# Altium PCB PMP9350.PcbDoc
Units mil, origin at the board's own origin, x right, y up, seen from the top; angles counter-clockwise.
Board outline 1440 x 2000 mil, 4 copper layers (Top Layer, MidLayer1, MidLayer2, Bottom Layer), stack 90 mil thick; 31 components, 13 nets, 63 pads, 44 vias.
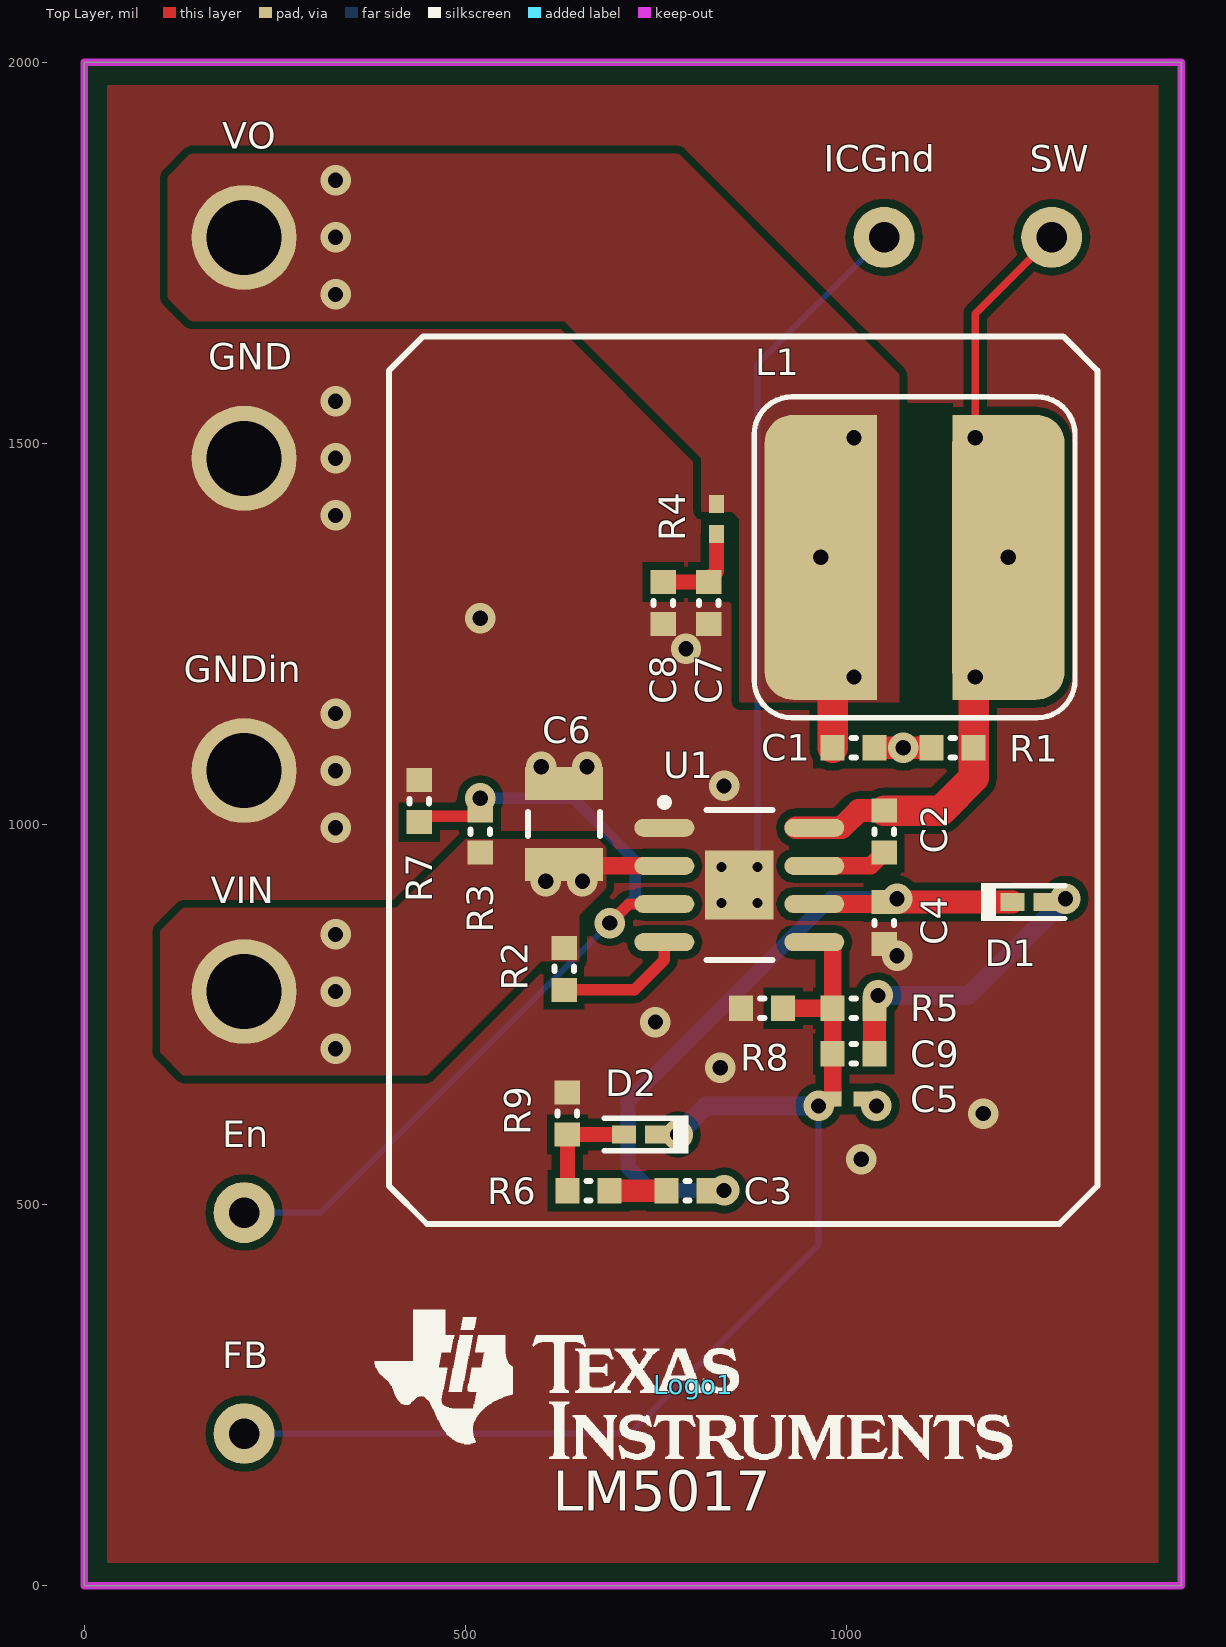
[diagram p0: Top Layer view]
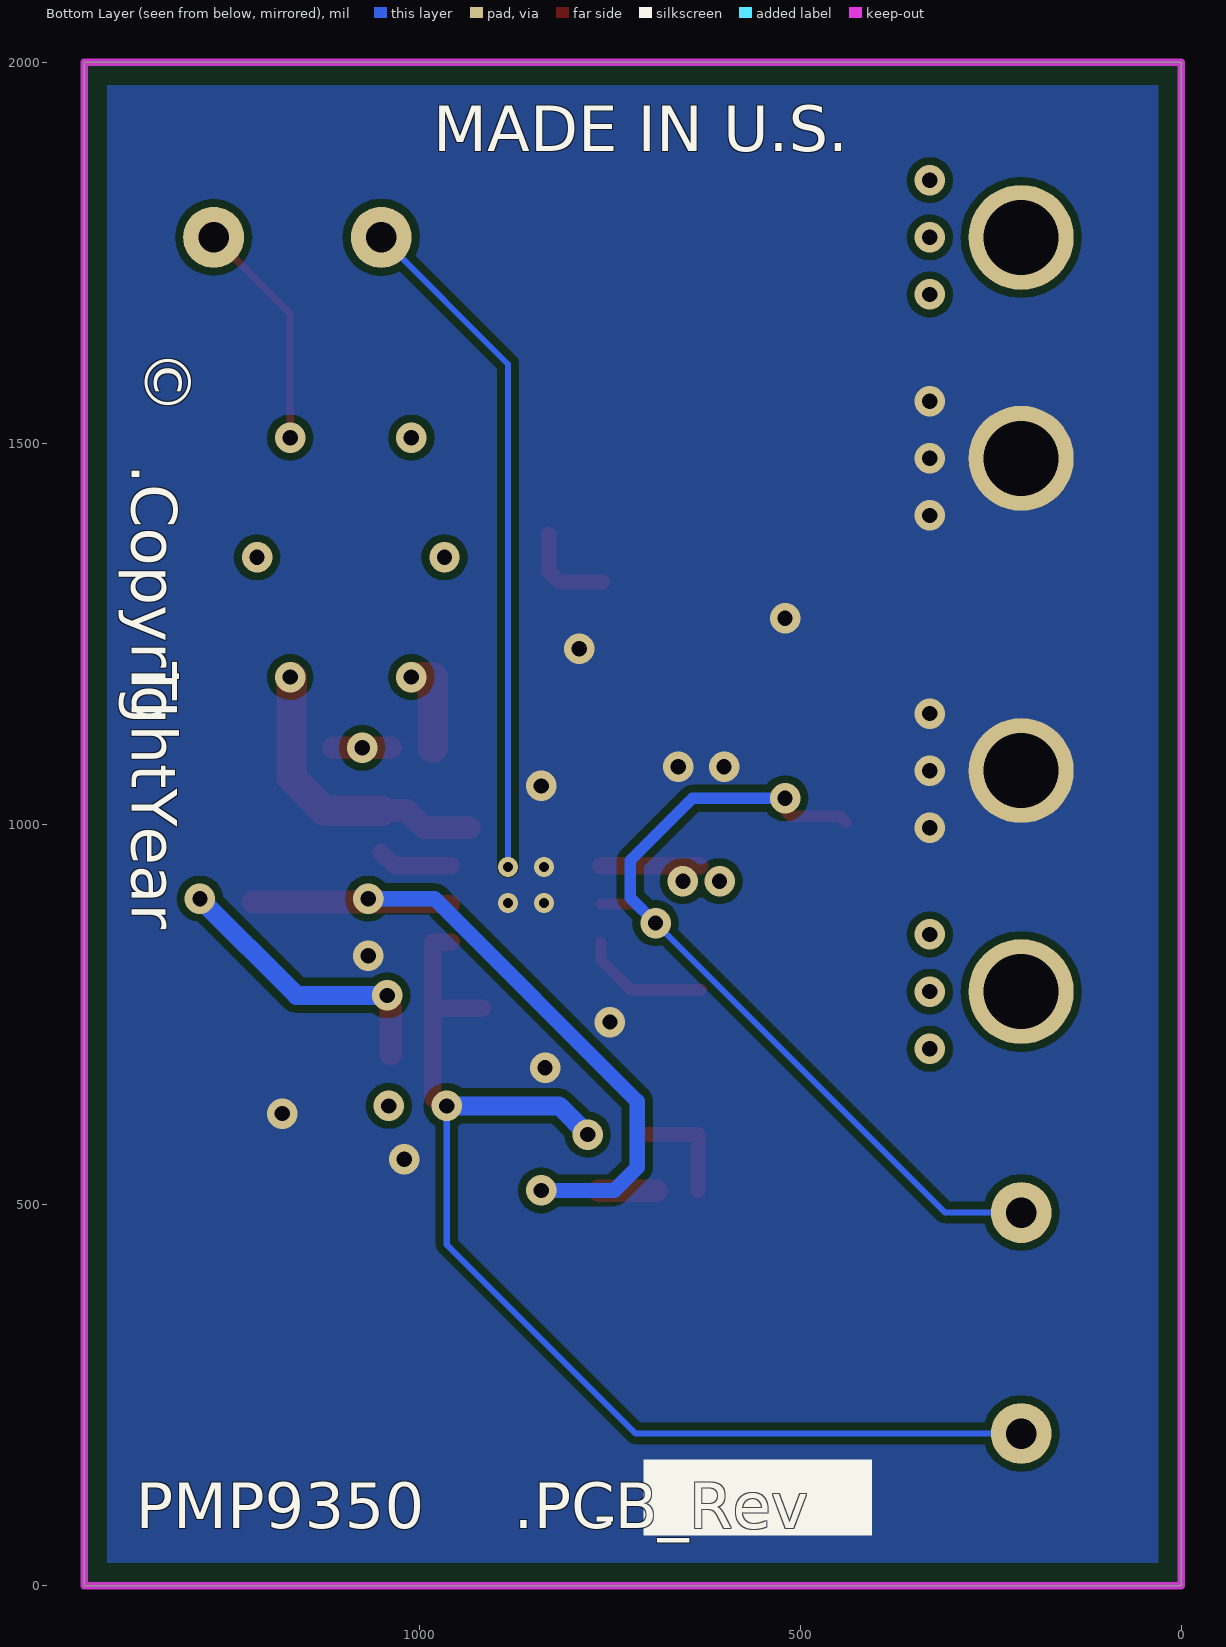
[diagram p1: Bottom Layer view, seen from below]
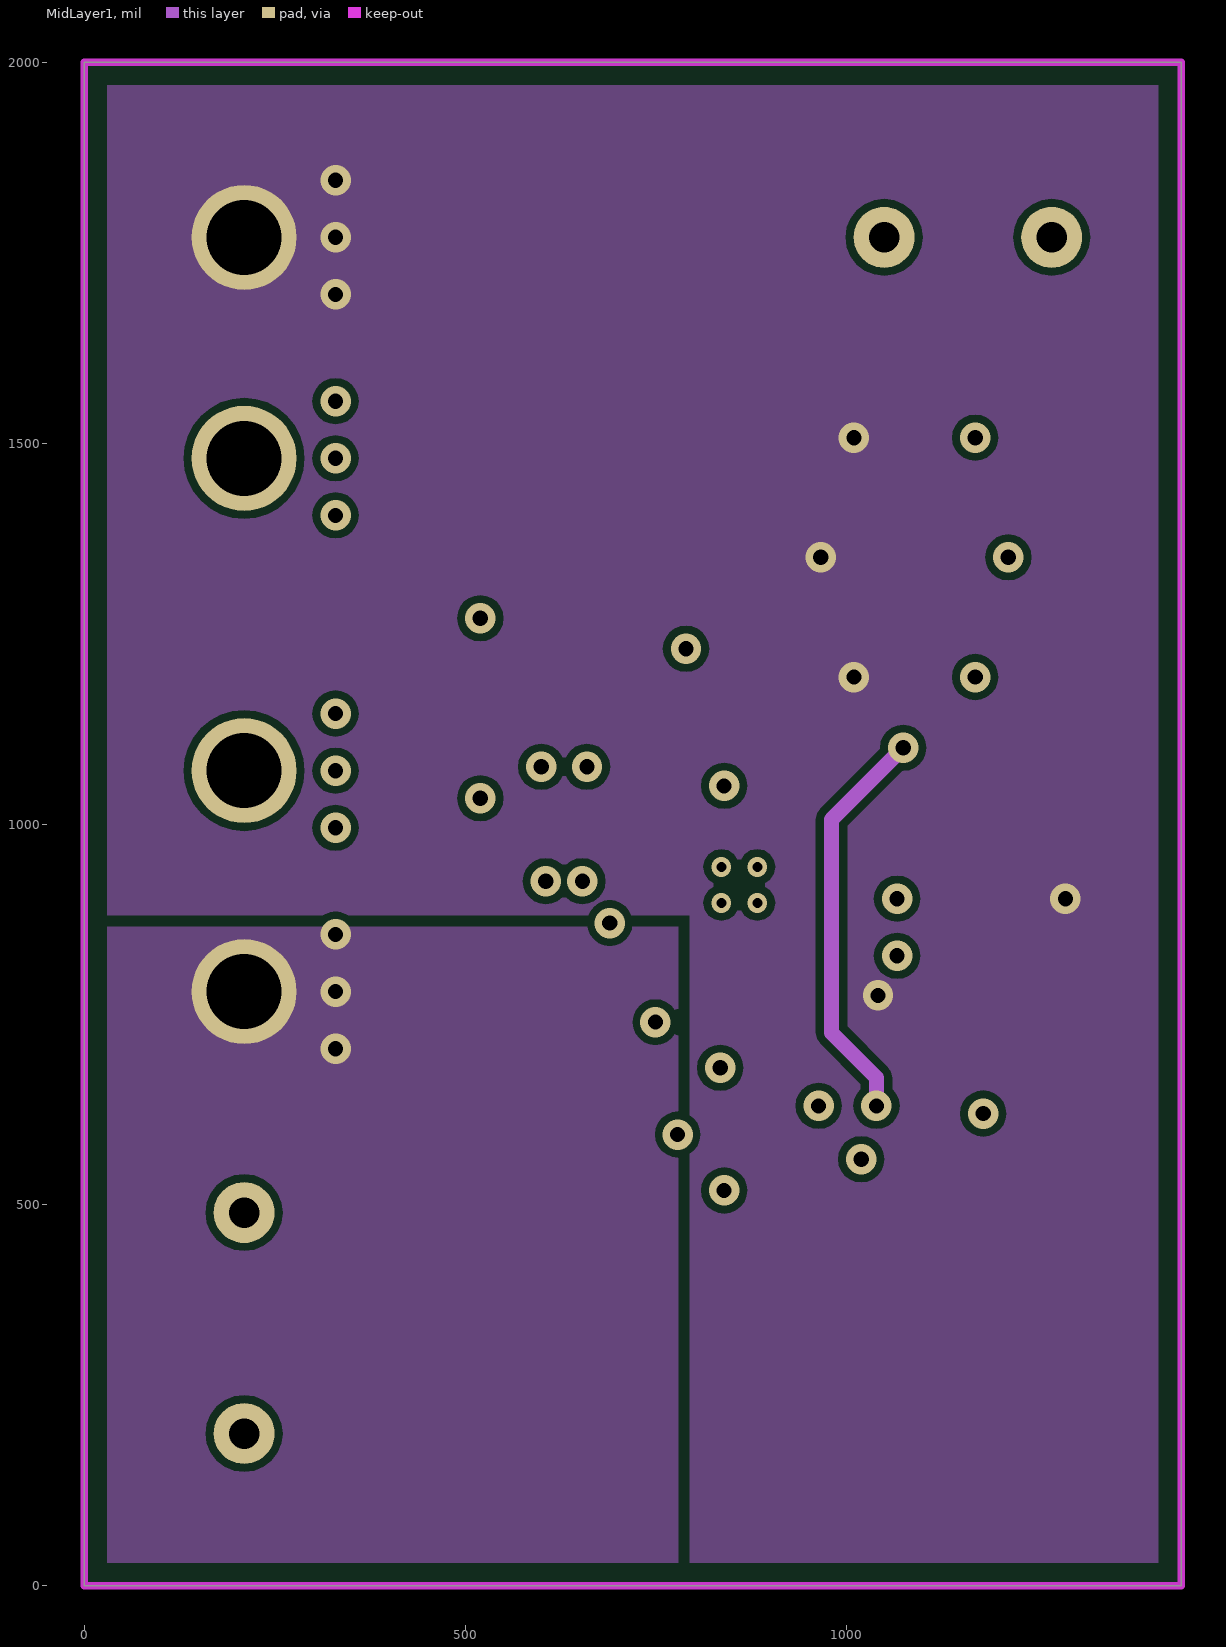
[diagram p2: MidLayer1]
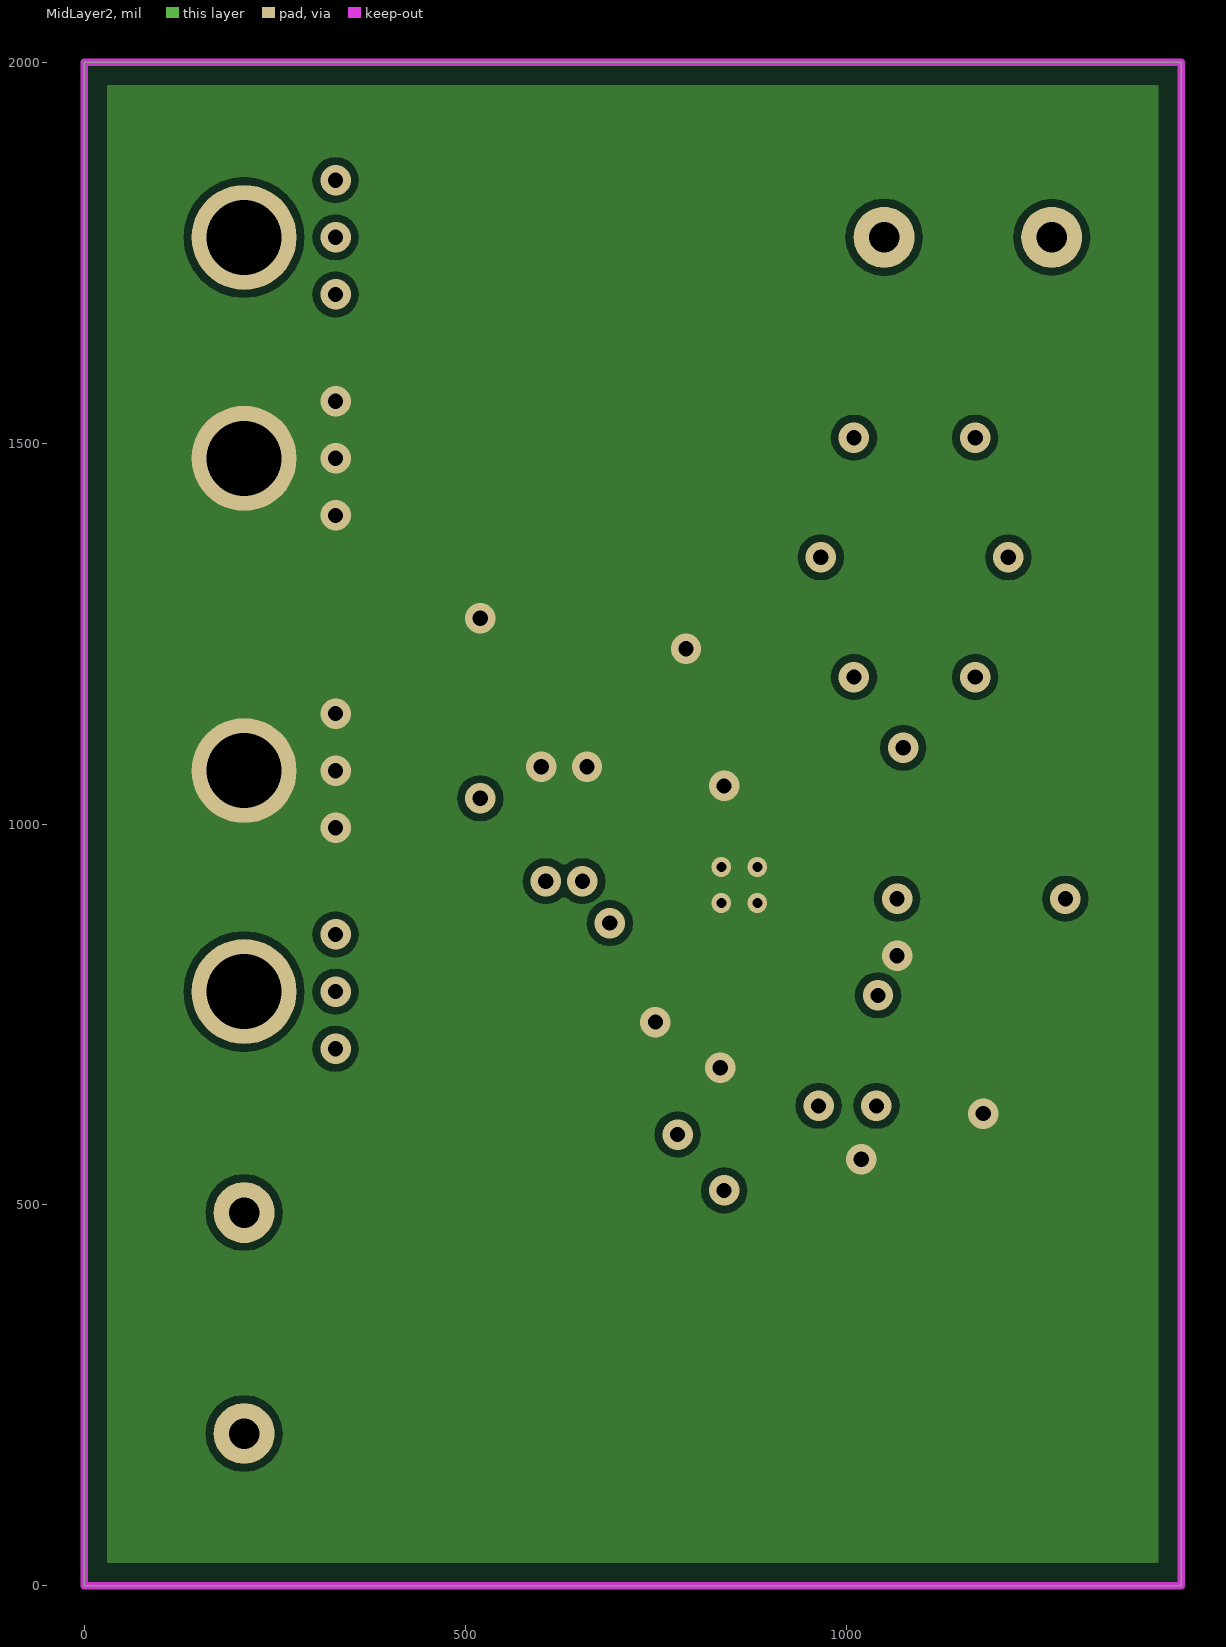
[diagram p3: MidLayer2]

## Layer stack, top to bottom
Top Solder: solder mask 0.4, Solder Resist, Dk 3.5
Top Layer: signal copper 1.4
Dielectric1: core 59.2, FR-4, Dk 4.8
MidLayer1: signal copper 1.4
Dielectric2: prepreg 12.6, FR-4, Dk 4.8
MidLayer2: signal copper 1.4
Dielectric3: core 12.6, FR-4, Dk 4.8
Bottom Layer: signal copper 1.4
Bottom Solder: solder mask 0.4, Solder Resist, Dk 3.5

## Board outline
0,0 1440,0 1440,2000 0,2000

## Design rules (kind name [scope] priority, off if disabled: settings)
AcuteAngle [All] p1: minimum=4.50000000000000E+0001 checktracksonly=FALSE
AssemblyTestPointUsage [All] p1: valid=2
Clearance Clearance_BoardEdge_MountingHoles [OnCopper and InComponentClass('Mounting Holes') vs IsKeepOut] p1: gap=40
Clearance Clearance_BoardEdge_Poly [OnCopper and InPoly vs IsKeepOut] p2: gap=25
Clearance Clearance_BoardEdge [OnCopper and Not InComponentClass('Logo') and not InComponentClass('FiducialMark') and not InRegion(1000,500,4000,800) and Not IsKeepout vs IsKeepOut] p3: gap=40
Clearance Clearance_Poly [InPolygon] p4: gap=10
Clearance [All] p5: gap=8
ComponentClearance ComponentClearance_Logo [InComponentClass(Logo)] p1: gap=50 collisioncheckmode=3 verticalgap=10 showdistances=FALSE
ComponentClearance ComponentClearance_ScrewToNut [(HasFootprint('NY PMS 440 0025 PH')) vs (HasFootprint('Keystone_1902C'))] p2: gap=5 collisioncheckmode=3 verticalgap=10 showdistances=FALSE
ComponentClearance ComponentClearance_MountingHoles [InComponentClass('Mounting Holes')] p3: gap=250 collisioncheckmode=3 verticalgap=100000 showdistances=FALSE
ComponentClearance ComponentClearance_SmallPassives [HasFootprint('0201*') or HasFootprint('0402*') or HasFootprint('0508') or HasFootprint('0603*') or HasFootprint('0612') or HasFootprint('0805*') or HasFootprint('0815*') or HasFootprint('0830*') or HasFootprint('1206*') or HasFootprint('1210*') or HasFootprint('1808*') or HasFootprint('1812*') or HasFootprint('1825*') or HasFootprint('2010*') or HasFootprint('2220*') or HasFootprint('2225*') or HasFootprint('2512*') or HasFootprint('2728*') or HasFootprint('3518*') vs HasFootprint('0201*') or HasFootprint('0402*') or HasFootprint('0508') or HasFootprint('0603*') or HasFootprint('0612') or HasFootprint('0805*') or HasFootprint('0815*') or HasFootprint('0830*') or HasFootprint('1206*') or HasFootprint('1210*') or HasFootprint('1808*') or HasFootprint('1812*') or HasFootprint('1825*') or HasFootprint('2010*') or HasFootprint('2220*') or HasFootprint('2225*') or HasFootprint('2512*') or HasFootprint('2728*') or HasFootprint('3518*')] p4: gap=10 collisioncheckmode=3 verticalgap=10 showdistances=FALSE
ComponentClearance ComponentClearance_THtoSMT [IsThruComponent vs IsSMTComponent] p5: gap=100 collisioncheckmode=3 verticalgap=100000 showdistances=FALSE
ComponentClearance ComponentClearance_THtoTH [IsThruComponent vs IsThruComponent] p6: gap=118.11 collisioncheckmode=3 verticalgap=100000 showdistances=FALSE
ComponentClearance [All] p7: gap=30 collisioncheckmode=3 verticalgap=10 showdistances=FALSE
DiffPairsRouting [All] p1: maxlimit=100 minlimit=10 mostfreqgap=10 toplayer_minwidth=15 toplayer_maxwidth=15 toplayer_prefwidth=15 midlayer1_minwidth=15 midlayer1_maxwidth=15 midlayer1_prefwidth=15 midlayer2_minwidth=15 midlayer2_maxwidth=15 midlayer2_prefwidth=15 bottomlayer_minwidth=15 bottomlayer_maxwidth=15 bottomlayer_prefwidth=15 maxuncoupledlength=1000
FabricationTestPointUsage TestPointUsage [All] p1: valid=2 allowmultiple=FALSE
FabricationTestpoint Testpoint [All] p1: side=3 testpointundercomponent=TRUE minsize=40 maxsize=100 preferedsize=60 minholesize=0 maxholesize=40 preferedholesize=32 testpointgrid=1 allowsidetop=TRUE allowsidebottom=TRUE usegrid=TRUE gridtolerance=0.01
FanoutControl Fanout_LCC [IsLCC] p1: bgadir=Out bgaviamode=Centered fanoutstyle=Auto fanoutdirection=Alternating viagrid=1 // Fanout_LCC (Default Rule)
FanoutControl Fanout_BGA [IsBGA] p2: bgadir=Out bgaviamode=Centered fanoutstyle=Auto fanoutdirection=Alternating viagrid=1 // Fanout_BGA (Default Rule)
FanoutControl Fanout_Default [All] p4: bgadir=Out bgaviamode=Centered fanoutstyle=Auto fanoutdirection=Alternating viagrid=1 // Fanout_Default (Default Rule)
FanoutControl Fanout_Small [(CompPinCount < 5)] p5: bgadir=Out bgaviamode=Centered fanoutstyle=Auto fanoutdirection=OutThenIn viagrid=1 // Fanout_Small (Default Rule)
HoleSize [All] p1: absolutevalues=TRUE maxlimit=251 minlimit=8 maxpercent=80.000 minpercent=20.000
MinimumAnnularRing [All] p1: minimumring=5
MinimumSolderMaskSliver MinimumSolderMaskSliver_Logo [InComponentClass('Logo') vs InComponentClass('Logo')] p1: minsoldermaskwidth=0.7
MinimumSolderMaskSliver [All] p2: minsoldermaskwidth=4
PlaneConnect [All] p1: planeconnectstyle=Relief reliefexpansion=10 reliefentries=4 reliefconductorwidth=10 reliefairgap=10
PolygonConnect [All] p1: connectstyle=Direct reliefconductorwidth=10 reliefentries=4 polygonreliefangle="90 Angle" airgapwidth=10
RoutingVias [All] p1: holewidth=16 width=34 viastyle="Through Hole" minholewidth=10 minwidth=20 maxholewidth=40 maxwidth=65
SMDToCorner [All] p1: distance=0
SilkToSilkClearance [All] p1: silktosilkclearance=5
SilkToSolderMaskClearance SilkscreenOverComponentPads [IsPad] p1: minsilkscreentomaskgap=5 clearancetoexposedcopper=TRUE
SolderMaskExpansion [All] p1: expansion=3
UnpouredPolygon [All] p1: allowunpoured=FALSE
Width [All] p1: maxlimit=100 minlimit=6 preferedwidth=10 checkconnectedcopper=TRUE
15 further rules are at their usual default settings.

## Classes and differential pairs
component class Hardware_ANSI-B: Logo1
component class Logo: Logo1

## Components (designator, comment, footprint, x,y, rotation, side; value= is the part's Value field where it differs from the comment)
C1 "GRM188R71H472KA01D" 0603L 1010,1100 r0 top
C2 "06035C104KAT2A" 0603L 1050,990 r270 top
C3 "EMK107BBJ106MA-T" 0603L 791.95,518.7 r180 top
C4 "C0603C105K4PACTU" 0603L 1050,870 r270 top
C5 "GRM155R71C102KA01D" 0402L 1002,639 r180 top
C6 "HMK325B7225KN-T" 1210L 630,1000 r90 top
C7 "EMK107BBJ106MA-T" 0603L 820,1290 r270 top
C8 "DNP" 0603L 760,1290 r270 top
C9 "GRM188R71C103KA01D" 0603L 1010,698.19 r180 top
D1 "" SOD-523 1240,897.56 r0 top
D2 "" SOD-523 730,592.44 r180 top
En "5002" Keystone5002 210,490 r0 top
FB "5002" Keystone5002 210,200 r0 top
GND "Suggest using a net name here" Keystone1502-2 210,1480 r0 top
GNDin "Suggest using a net name here" Keystone1502-2 210,1070 r90 top
ICGnd "5001" Keystone5001 1050,1770 r0 top
L1 "744776168" WE-PD2-XL 1090,1350 r180 top
Logo1 "Texas Instruments" TI_Stacked_Overlay_Small 800,264 r0 top
R1 "CRCW0603130KFKEA" 0603L 1140,1099.99 r180 top
R2 "CRCW0603196KFKEA" 0603L 630,810 r270 top
R3 "CRCW0603124KFKEA" 0603L 520,990 r270 top
R4 "CRCW06030000Z0EA" 0402L 830,1400 r90 top
R5 "RC0603FR-0718KL" 0603L 1010,758.19 r0 top
R6 "CRCW060310K0FKEA" 0603L 661.95,518.7 r0 top
R7 "CRCW060314K7FKEA" 0603L 440,1030 r270 top
R8 "CRCW06032K00FKEA" 0603L 890,758.19 r0 top
R9 "CRCW060310K0FKEA" 0603L 634.39,620 r270 top
SW "5000" Keystone5000 1270,1770 r0 top
U1 "LM5017MR" MRA08A_N 860,920 r0 top
VIN "Suggest using a net name here" Keystone1502-2 210,780 r0 top
VO "Suggest using a net name here" Keystone1502-2 210,1770 r0 top

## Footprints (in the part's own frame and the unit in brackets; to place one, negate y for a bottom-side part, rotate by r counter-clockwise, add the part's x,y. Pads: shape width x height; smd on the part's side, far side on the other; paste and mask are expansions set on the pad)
0402L [mm] "0402 from SM-752 data"
  rect 0.6x0.5 smd: 1(-0.5,0) 2(0.5,0)
  body extent -0.55,-0.3 0.55,0.3, height 0.6
0603L [mm] "0603 from SM-752 data"
  rect 0.8x0.85 smd: 1(-0.7,0) 2(0.7,0)
  silkscreen extent -0.07,-0.33 0.07,0.33, body extent -0.87,-0.47 0.87,0.47, height 0.85
1210L [mm] "1210 from SM-752 data"
  rect 1.1x2.6 smd: 1(-1.35,0) 2(1.35,0)
  silkscreen extent -0.4,-1.2 0.4,1.2, body extent -1.7,-1.35 1.7,1.35, height 1.35
Keystone1502-2 [mm] "Double Turret"
  round 3.5 hole 2.5: 1(0,0)
  body extent -1.6,-1.6 1.59,1.6, height 5.62
Keystone5000 [mil] "For Keystone 500x miniature loop terminals"
  round 80 hole 40: 1(0,0)
  body extent -49,-49 49,49, height 182
Keystone5001 [mil] "For Keystone 500x miniature loop terminals"
  round 80 hole 40: 1(0,0)
  body extent -49,-49 49,49, height 182
Keystone5002 [mil] "For Keystone 500x miniature loop terminals"
  round 80 hole 40: 1(0,0)
  body extent -49,-49 49,49, height 182
MRA08A_N [mm] "SOIC, 8-Leads, Body 4.9x3.9mm, Pitch 1.27mm, Exposed Pad, IPC Medium Density"
  oval 2x0.6 smd: 1(-2.5,1.905) 2(-2.5,0.635) 3(-2.5,-0.635) 4(-2.5,-1.905) 5(2.5,-1.905) 6(2.5,-0.635) 7(2.5,0.635) 8(2.5,1.905)
  rect 2.29x2.29 smd: 9(0,0)
  silkscreen extent -2.62,-2.5 1.1,2.88, body extent -2,-2.5 2,2.5, height 1.68
SOD-523 [mm] "NXP Semiconductor recommended land pattern, nominal STEP model"
  rect 0.8x0.6 smd paste-0.05: 1(-0.55,0) 2(0.55,0)
  silkscreen extent -1.6,-0.64 1.2,0.64, body extent -0.8,-0.4 0.8,0.4, height 0.72
TI_Stacked_Overlay_Small [mil]
  silkscreen extent -418,-98 418,98
WE-PD2-XL [mm] "Wurth Elektronik recommended land pattern"
  rrect50% 3.75x9.5 smd: 1(-3.125,0) 2(3.125,0)
  rect 1.524x1.524 smd: 1(-2.02,3.99) 1(-2.02,-3.99) 2(2.02,3.99) 2(2.02,-3.99)
  silkscreen extent -5.35,-5.35 5.35,5.35, body extent -4.94,-4.5 4.94,4.5, height 5.9

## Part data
C1: "CAP, CERM, 4700pF, 50V, +/-10%, X7R, 0603"
C2: "CAP, CERM, 0.1uF, 50V, +/-10%, X7R, 0603"
C3 C7: "CAP, CERM, 10uF, 16V, +/-20%, X5R, 0603"
C4: "CAP, CERM, 1uF, 16V, +/-10%, X5R, 0603"
C5: "CAP, CERM, 1000pF, 16V, +/-10%, X7R, 0402"
C6: "CAP, CERM, 2.2uF, 100V, +/-10%, X7R, 1210"
C8: library part GRM21BR71E225KA73L, "CAP, CERM, 2.2uF, 25V, +/-10%, X7R, 0805"
C9: "CAP, CERM, 0.01uF, 16V, +/-10%, X7R, 0603"
D1 D2: library part SDM10U45-7-F, "Diode, Schottky, 45V, 0.1A, SOD-523"
En FB: "Test Point, TH, Miniature, White"
GND GNDin VIN VO: library part 1502-2, "Terminal, Turret, TH, Double"
ICGnd: "Test Point, TH, Miniature, Black"
L1: "Inductor, Drum Core, Ferrite, 68uH, 1.19A, 0.138 ohm, SMD"
Logo1: library part TI_Logo, "Texas Instrument Corporate Signature"
R1: "RES, 130k ohm, 1%, 0.1W, 0603"
R2: "RES, 196k ohm, 1%, 0.1W, 0603"
R3: "RES, 124k ohm, 1%, 0.1W, 0603"
R4: "RES, 0 ohm, 5%, 0.1W, 0603"
R5: "RES, 18.0k ohm, 1%, 0.1W, 0603"
R6 R9: "RES, 10.0k ohm, 1%, 0.1W, 0603"
R7: "RES, 14.7k ohm, 1%, 0.1W, 0603"
R8: "RES, 2.00k ohm, 1%, 0.1W, 0603"
SW: "Test Point, TH, Miniature, Red"
U1: library part LM5017

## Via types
v1: diameter 40, hole 20, Top Layer to Bottom Layer, tented both sides, 40 vias
v2: diameter 25.98, hole 12.99, Top Layer to Bottom Layer, tented both sides, 4 vias

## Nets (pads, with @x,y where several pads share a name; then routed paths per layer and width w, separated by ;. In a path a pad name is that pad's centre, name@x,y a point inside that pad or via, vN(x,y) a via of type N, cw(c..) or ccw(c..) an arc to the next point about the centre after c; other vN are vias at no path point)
BST: C2.2 U1.7 | length 98.8
  Top Layer w23: U1.7 1032.56,945 C2.2
EN: En.1 R3.1 R7.2 U1.3 | length 1138.4
  Top Layer w15: R7.2 447.56,1010 512.44,1010 R3.1 ; v1(690,870) 715,895 U1.3
  Bottom Layer w8: En.1 310,490 v1(690,870)
  Bottom Layer w15: v1(520,1033.73) 641.53,1033.73 723.22,952.04 723.22,903.22 v1(690,870)
FB: C5.2 C9.2 D2.1 FB.1 R5.1 R8.2 U1.5 | length 1532.9
  Top Layer w23: R8.2 R5.1 ; U1.5 982.44,845 R5.1 ; C5.2@982.44,640.32 C9.2 R5.1
  Bottom Layer w8: FB.1 716,200 964,448 v1(964,630)
  Bottom Layer w25: v1(779,592.44) 816.56,630 v1(964,630)
GND: C4.2 C6.2 C7.2 C8.2 GND.1 GNDin.1 ICGnd.1 R7.1 R8.1 R9.1 U1.1 U1.9 | length 895.3
  Bottom Layer w8: v2(883.62,943.62) 883.62,1603.62 ICGnd.1
  other v1: 1019.92,560 1180,620 834.9,680 749.84,740 1067,827 330,995 840,1050 330,1070 600,1075 660.05,1075 330,1145 790,1230 520,1270 330,1405 330,1480 330,1555
  other v2: 836.38,896.38 883.62,896.38 836.38,943.62
NetC1_2: C1.2 C5.1 R1.2 | length 608.3
  Top Layer w30: C1.2 v1(1075,1100) R1.2
  MidLayer1 w20: v1(1040,630) 1040,667 981,726 981,1006 v1(1075,1100)
NetC3_2: C3.2 R6.2 | length 74.9
  Top Layer w30: R6.2 C3.2
NetC7_1: C7.1 C8.1 R4.1 | length 124.6
  Top Layer w10: C7.1@816.06,1317.56 C7.1@820,1321.5
  Top Layer w20: C8.1 C7.1@816.06,1317.56 ; C7.1@820,1321.5 830,1331.5 R4.1
NetD2_2: D2.2 R6.1 R9.2 | length 147.7
  Top Layer w20: R6.1 R9.2 D2.2
RON: R2.2 U1.4 | length 171.2
  Top Layer w15: R2.2 722.44,782.44 761.57,821.57 U1.4
SW: C2.1 L1.1 R1.1 SW.1 U1.8 | length 697.6
  Top Layer w10: v1(1169.53,1507.09) 1169.53,1669.53 SW.1
  Top Layer w30: U1.8@934,995 U1.8 994,995 1016.56,1017.56 C2.1
  Top Layer w40: C2.1 1124.56,1017.56 1167.56,1060.56 R1.1 L1.1@1167.56,1192.91
  other v1: 1169.53,1192.91 1213.03,1350
VCC: C3.1 C4.1 D1.1 U1.6 | length 948.4
  Top Layer w23: U1.6 C4.1@1050,895
  Top Layer w30: C4.1 D1.1
  Bottom Layer w20: v1(840,519) 744.2,519 714,549.2 714,636 980,902 v1(1067,902)
VIN: C6.1 R2.1 R3.2 U1.2 VIN.1 | length 129.5
  Top Layer w23: C6.1@632.09,945 U1.2
  other v1: 330,705 330,780 330,855 606,925 654,925
VOUT: C1.1 C9.1 D1.2 L1.2 R4.2 R5.2 VO.1 | length 479.5
  Top Layer w30: C9.1 R5.2
  Top Layer w40: C1.1 982.44,1192.91 v1(1010.47,1192.91)
  Bottom Layer w25: v1(1042,775) 1161,775 v1(1288,902)
  other v1: 966.97,1350 1010.47,1507.09 330,1695 330,1770 330,1845

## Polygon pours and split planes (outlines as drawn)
VOUT on MidLayer1 "MidLayer1-VOUT1" (solid, pour order 9): 1440,2000 0,2000 0,880 795,880 795,0 1440,0
VIN on MidLayer1 "MidLayer1-VIN" (solid, pour order 10): 0,0 780,0 780,865 0,865
VIN on Top Layer "Top Layer-VIN" (solid, pour order 11): 410,890 500,980 675,980 685,970 685,915 650,880 650,820 600,820 450,670 130,670 100,700 100,860 130,890
GND on Top Layer "Top Layer-GND" (solid, pour order 13): 0,0 1440,0 1440,2000 0,2000
VOUT on Top Layer "Top Layer-VOUT" (solid, pour order 12): 1070,1160 1070,1590 780,1880 140,1880 110,1850 110,1690 140,1660 630,1660 810,1480 810,1410 850,1410 860,1400 860,1160
GND on Bottom Layer "Bottom Layer-GND" (solid, pour order 14): 0,0 1440,0 1440,2000 0,2000
GND on MidLayer2 "MidLayer2-GND" (solid, pour order 8): 1440,2000 0,2000 0,0 1440,0

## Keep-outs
Keep-Out Layer:
  the board outline again, w10
  text ".Layer_Name" at -613,-1688.49 h60

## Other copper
Top Layer:
  pour cut-out: 1070,1552.09 1140,1552.09 1140,1121.99 1070.01,1121.99 1070,1122
  pour cut-out: 1050,1719.68 cw(c1050,1770) 999.68,1770 cw(c1050,1770) 1050,1820.32 cw(c1050,1770) 1100.32,1770 cw(c1050,1770)
  text ".Layer_Name" at -613,-1688.49 h60
MidLayer2:
  pour cut-out: 1050,1719.68 cw(c1050,1770) 999.68,1770 cw(c1050,1770) 1050,1820.32 cw(c1050,1770) 1100.32,1770 cw(c1050,1770)
Bottom Layer:
  pour cut-out: 1050,1719.68 cw(c1050,1770) 999.68,1770 cw(c1050,1770) 1050,1820.32 cw(c1050,1770) 1100.32,1770 cw(c1050,1770)
  text ".Layer_Name" at -613,-1688.49 h60

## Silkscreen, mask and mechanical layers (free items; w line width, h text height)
Top Overlay:
  lines w7.78: 400,525 400,1595 445,1640 1285,1640 1330,1595 1330,525 1280,475 450,475 400,525
  text "LM5017" at 615,81 h90
  text ".Layer_Name" at -613,-1688.49 h60
Bottom Overlay:
  rectangle: 406,66 706,166
  text "MADE IN U.S." at 982,1883 h60
  text "©" at 1381,1622 h105 r90
  text ".CopyrightYear" at 1377.48,1472 h60 r90
  text "TI" at 1377.48,1212 h60 r90
  text ".PCB_Rev" at 876,76 h60
  text "PMP9350" at 1372,76 h60
  text "-" at 771,65.5 h60
  text ".Layer_Name" at -613,-1688.49 h60
Top Paste:
  text ".Layer_Name" at -613,-1688.49 h60
Bottom Paste:
  text ".Layer_Name" at -613,-1688.49 h60
Top Solder:
  text ".Layer_Name" at -613,-1688.49 h60
  text ".Layer_Name" at -613,-1688.49 h60
Bottom Solder:
  text ".Layer_Name" at -613,-1688.49 h60
Drill Guide:
  text ".Layer_Name" at -613,-1688.49 h60
M1 Board Outline:
  the board outline again, w10
  text ".Layer_Name" at -613,-1688.49 h60
M2 Board Dimensions:
  rectangle: -1065.5,-1240.5 -690.5,-1115.5
  rectangle: -1190.5,-1115.5 -1065.5,-990.5
  lines w7: -1190.5,-1115.5 -190.5,-1115.5 ; -1065.5,-1240.5 -1065.5,-990.5 ; -940.5,-1240.5 -940.5,-990.5 ; -690.5,-1240.5 -690.5,-990.5 ; -440.5,-1240.5 -440.5,-990.5 ; -1190.5,-1240.5 -1190.5,-990.5 -190.5,-990.5 -190.5,-1240.5 -1190.5,-1240.5
  lines w10: -1190.5,-1305.5 -1190.5,-1285.5 ; -1130.5,-1315.5 -1190.5,-1295.5 ; -1130.5,-1275.5 -1190.5,-1295.5 ; -966.42,-1295.5 -1190.5,-1295.5 ; -414.58,-1295.5 -190.5,-1295.5 ; -250.5,-1315.5 -190.5,-1295.5 ; -250.5,-1275.5 -190.5,-1295.5 ; -190.5,-1305.5 -190.5,-1285.5
  text "1000 (mil)" at -956.42,-1331.49 h60
  text ".Layer_Name" at -613,-1688.49 h60
M3 3D STEP Top:
  text ".Layer_Name" at -613,-1688.49 h60
M4 3D STEP Bottom:
  text ".Layer_Name" at -613,-1688.49 h60
M5 Assembly Top:
  lines w10: -1482,-1760.17 5118,-1760.17 ; -1482,-1556.83 5120,-1556.83 ; -1482,-1353.5 -1482,-1963.5 2523,-1963.5 5120,-1963.5 5120,-1353.5 -1481.5,-1353.5 -1481.5,-1963.5 94,-1963.5 ; 983,-1963.5 983,-1353.5 ; 2250,-1556.83 2250,-1353.5 ; 3090,-1556.83 3090,-1353.5 ; 3712,-1970 3712,-1767.17
  text "TABLE 1" at 316.85,1648 h40
  text "COMPONENTS MARKED 'DNP' SHOULD NOT BE POPULATED." at -36.5,-1148.5 h60
  text "ASSEMBLY VARIANT:" at -37,-1264 h60
  text ".VariantName" at 999,-1264 h60
  text "PCB VIEWED FROM TOP SIDE" at -1418.5,-1485.67 h60
  text "BOARD #:" at 1058,-1485.67 h60
  text ".PRJ_Number" at 1603.5,-1485.67 h60
  text "REV:" at 2448,-1485.67 h60
  text ".PCB_Rev" at 2739.5,-1485.67 h60
  text "SVN REV:" at 3286,-1485.67 h60
  text ".VersionControl_RevNumber" at 3792,-1485.67 h60
  text "IGNORE ->" at -1418.5,-1688.49 h60
  text "PLOT NAME =" at -1418.5,-1894.34 h60
  text ".plot_File_Name" at -613,-1894.34 h60
  text "GENERATED    :" at 1060,-1894.34 h60
  text ".Print_Date" at 1929.5,-1894.34 h60
  text ".Print_Time" at 2658.5,-1894.34 h60
  text "TEXAS INSTRUMENTS" at 3923,-1894.34 h60
M6 Assembly Bottom:
  lines w10: -1482.5,-1557.33 5119.5,-1557.33 ; -1480.5,-1760.67 5119.5,-1760.67 ; -74.5,-1970.5 -74.5,-1767.67 ; 547.5,-1557.33 547.5,-1354 ; 1387.5,-1557.33 1387.5,-1354 ; 2654.5,-1964 2654.5,-1354 ; 3543.5,-1964 5119,-1964 5119,-1354 -1482.5,-1354 -1482.5,-1964 1114.5,-1964 5119.5,-1964 5119.5,-1354
  text "COMPONENTS MARKED 'DNP' SHOULD NOT BE POPULATED." at 4912,-1148 h60
  text ".VariantName" at 3868,-1264 h60
  text "ASSEMBLY VARIANT:" at 4907,-1264 h60
  text ".VersionControl_RevNumber" at -154.5,-1486.17 h60
  text "SVN REV:" at 351.5,-1486.17 h60
  text ".PCB_Rev" at 898,-1486.17 h60
  text "REV:" at 1189.5,-1486.17 h60
  text ".PRJ_Number" at 2034,-1486.17 h60
  text "BOARD #:" at 2579.5,-1486.17 h60
  text "PCB VIEWED FROM BOTTOM SIDE" at 5056,-1486.17 h60
  text "IGNORE ->" at 1357.85,-1688.49 h60
  text "TEXAS INSTRUMENTS" at -285.5,-1894.84 h60
  text ".Print_Time" at 979,-1894.84 h60
  text ".Print_Date" at 1708,-1894.84 h60
  text "GENERATED    :" at 2577.5,-1894.84 h60
  text ".plot_File_Name" at 4250.5,-1894.84 h60
  text "PLOT NAME =" at 5056,-1894.84 h60
M9 Title Sheet:
  drawing of 57 lines, arcs and shapes, not listed
  text "1" at -450.16,7206.5 h70
  text "2" at 2045.5,7206.5 h70
  text "3" at 4534.84,7206.5 h70
  text "4" at 7041.51,7206.5 h70
  text "5" at 9540.5,7206.5 h70
  text "6" at 12045.5,7206.5 h70
  text "A" at -1606.5,6063.5 h70
  text "A" at 13193.5,6063.5 h70
  text "B" at -1606.5,3683.5 h70
  text "B" at 13193.5,3683.5 h70
  text "C" at -1606.5,1308.5 h70
  text "C" at 13193.5,1308.5 h70
  text "PROJECT TITLE:" at 10153.5,-552.5 h45
  text ".PRJ_Title" at 10203.5,-685.83 h70
  text "DESIGNED FOR:" at 10153.5,-853.5 h45
  text ".PRJ_Customer" at 10203.5,-993.5 h70
  text "D" at -1606.5,-1061.5 h70
  text "D" at 13193.5,-1061.5 h70
  text "FILE NAME:" at 10153.5,-1153.5 h45
  text ".PCB_File_Name_No_Path" at 10203.5,-1273.5 h70
  text "Texas Instruments (TI) and/or its licensors do not warrant the accuracy or completeness of this specification" at 5184,-1435.34 h45
  text "ENGINEER:" at 10153.5,-1443.5 h45
  text "LAYOUT BY:" at 11658.5,-1443.5 h45
  text "or any information contained therein. TI and/or its licensors do not warrant that this design will meet" at 5139.01,-1548 h45
  text ".PRJ_Engineer" at 10203.5,-1598.49 h70
  text ".PCB_Layout" at 11709,-1598.49 h70
  text "the specifications, will be suitable for your application or fit for any particular purpose, or will operate in" at 5139.01,-1660.67 h45
  text ".Layer_Name" at -613,-1688.49 h60
  text "ALTIUM DESIGNER VERSION:" at 11658.5,-1753.5 h45
  text "an implementation. TI and/or its licensors do not warrant that the design is production worthy. You should" at 5139.01,-1773.33 h45
  text "completely validate and test your design implementation to confirm the system functionality for your application." at 5184,-1886 h45
  text ".print_Scale" at 10203.5,-1886.83 h70
  text ".Application_BuildNumber" at 11709,-1886.83 h70
  text "1" at -450.16,-2093.5 h70
  text "2" at 2045.5,-2093.5 h70
  text "3" at 4534.84,-2093.5 h70
  text "4" at 7041.51,-2093.5 h70
  text "5" at 9540.5,-2093.5 h70
  text "6" at 12045.5,-2093.5 h70
M10 Fab Notes:
  drawing of 212 lines, arcs and shapes, not listed
  text "DESIGN INFORMATION" at 11191.02,5980 h60
  text "(REFER ALSO ARRAY/PANEL PROFILING INFORMATION)" at 10829.46,5818.29 h60
  text "BOARD SIZE" at 10143.46,5814 h60
  text "1440MIL" at 10605.78,5686.18 h60
  text "X" at 11111.46,5686.18 h60
  text "2000MIL" at 11342.78,5686.18 h60
  text "Number of Layers :" at 10546.46,5489 h60
  text "2" at 11641.27,5479 h60
  text "MIN. TRACK WIDTH:" at 10546.46,5350 h60
  text "8" at 11642.7,5350 h60
  text "MIL" at 11797.46,5350 h60
  text "MIN. CLEARANCE:" at 10546.46,5218 h60
  text "8" at 11642.7,5218 h60
  text "MIL" at 11797.46,5218 h60
  text "MIN. VIA PAD SIZE:" at 10546.46,5086 h60
  text "24" at 11612.71,5086 h60
  text "MIL" at 11797.46,5086 h60
  text "0.05mm (2MIL)" at 11241.46,4944.29 h60
  text "MINIMUM ANNULAR RING" at 10217.23,4940 h60
  text "EXTERNAL" at 11949.46,4940 h60
  text "PER" at 10417.23,4822 h60
  text "IPC-D-275 CLASS 2 LEVEL C" at 10637.23,4822 h60
  text "MIL, HOLES" at 12125.46,4709.71 h60
  text "+/-" at 11733,4709 h60
  text "+/-" at 12587,4709 h60
  text "REGISTRATION TOLERANCES:" at 10217.23,4704 h60
  text "METAL" at 11417,4704 h60
  text "5" at 11993.2,4704 h60
  text "3" at 12826.2,4704 h60
  text "MIL" at 12942.46,4704 h60
  text "MATERIAL:" at 10142.46,4494.54 h60
  text "FR-4" at 12664,4372 h60
  text "FR-4 High Tg" at 11128.9,4354.21 h60
  text "FR-408" at 10563.46,4345.64 h60
  text "X" at 11864,4346 h60
  text "OTHER" at 12051.46,4345.64 h60
  text "62 MIL (1.6mm) +/-10%" at 10883.56,4182.92 h60
  text "THICKNESS:" at 10217.23,4178.64 h60
  text "X" at 10755.4,4178.64 h60
  text "OTHER" at 12168.46,4178.64 h60
  text "TOLERANCE:" at 10217.23,4020.64 h60
  text "X" at 11056.53,4020.64 h60
  text "ANSI IPC-6012 TYPE 3 CLASS 2" at 11243.48,4020.64 h60
  text "OTHER +/-" at 11243.46,3864.64 h60
  text "BOW & TWIST:" at 10217.23,3707.64 h60
  text "X" at 11056.53,3707.64 h60
  text "ANSI IPC-6012 TYPE 3 CLASS 2" at 11243.48,3707.64 h60
  text "OTHER +/-" at 11243.46,3549.13 h60
  text "COPPER THICKNESS (FINISHED):" at 10142.46,3413.64 h60
  text "1.4MIL (1oz)" at 11022.46,3260.92 h60
  text "2MIL (1.4oz)" at 11789.46,3260.92 h60
  text "2.8MIL (2oz)" at 12516.46,3260.92 h60
  text "OUTER:" at 10499.46,3256.64 h60
  text "X" at 10894,3256 h60
  text "1.4MIL (1oz)" at 11022.46,3103.92 h60
  text "2.8MIL (2oz)" at 11789.46,3103.92 h60
  text "N/A" at 12516,3104.29 h60
  text "INNER SIGNAL:" at 10210.38,3099.64 h60
  text "X" at 10895.42,3099.64 h60
  text "DRILLING:" at 10142.46,2960.64 h60
  text "REFERENCE:" at 10217.23,2843.64 h60
  text "X" at 10865.46,2843.64 h60
  text "AS SHOWN" at 11052.46,2843.64 h60
  text "X" at 11766.46,2843.64 h60
  text "NC_DRILL FILES" at 11903.46,2843.64 h60
  text "PTH MIN COPPER THICKNESS:" at 10217.23,2685.64 h60
  text "X" at 11567.46,2685.64 h60
  text "1MIL" at 11704.46,2685.64 h60
  text "OTHER" at 12201.46,2685.64 h60
  text "BOARD FINISH:" at 10142.46,2526.64 h60
  text "SILKSCREEN:" at 10297.68,2408.64 h60
  text "X" at 11246.46,2408.64 h60
  text "TOP" at 11372.46,2408.64 h60
  text "X" at 11756.46,2408.64 h60
  text "BOTTOM" at 11883.46,2408.64 h60
  text "SILKSCREEN COLOR:" at 10297.68,2241.64 h60
  text "X" at 11245.42,2241.64 h60
  text "WHITE" at 11372.46,2241.64 h60
  text "OTHER" at 11883.46,2241.64 h60
  text "SOLDER RESIST COLOR:" at 10297.68,2071.64 h60
  text "X" at 10865.42,1912.44 h60
  text "GREEN" at 10992.46,1912.44 h60
  text "BLUE" at 11583.46,1912.44 h60
  text "OTHER" at 12121.46,1912.44 h60
  text "IMMERSION GOLD (ENIG)" at 11203.46,1723.92 h60
  text "ENEPIG" at 12541,1720.64 h60
  text "SURFACE FINISH:" at 10142.46,1719.64 h60
  text "HASL" at 12587.27,1572 h60
  text "X" at 11717,1564 h60
  text "IMM. TIN/SILVER OR EQUIV" at 10472,1562.64 h60
  text "OTHER" at 11903.46,1562.64 h60
  text "X" at 11007,1391 h60
  text "ARRAY/PANEL:" at 10142.46,1383.64 h60
  text "CUT AND TRIM PER MECH LAYER 1" at 11203.46,1379.35 h60
  text "N.C. ROUTE" at 11203.46,1227.64 h60
  text "V. SCORE" at 12069.46,1227.64 h60
  text "CERTIFICATION:" at 10142.46,1090.64 h60
  text "MATERIALS AND WORKMANSHIP FOR ALL PCBS" at 10867.46,1090.64 h60
  text "TO MEET OR EXCEED THE REQUIREMENTS OF:" at 10867.46,992.64 h60
  text "X" at 10493.96,856.13 h60
  text "ANSI IPC-A-600F CLASS ->" at 10632.96,856.13 h60
  text "X" at 12272.02,856.13 h60
  text "2" at 12390.96,856.14 h60
  text "1" at 12075.96,854.64 h60
  text "3" at 12744.96,854.64 h60
  text "X" at 10496.02,696.64 h60
  text "UL 94V-0" at 10632.96,696.64 h60
  text "X" at 11308.02,696.64 h60
  text "RoHS" at 11444.96,696.64 h60
  text "OTHER" at 12089.36,696.64 h60
  text "PER ORDER" at 12486.42,696.64 h60
  text "ADDITIONAL REQUIREMENTS:" at 10142.46,555.64 h60
  text "MICROSECTION:" at 10217.23,440.64 h60
  text "YES" at 11122.96,440.64 h60
  text "X" at 12448,297 h60
  text "REQUIRED" at 11984.46,284.49 h60
  text "BARE BOARD ELEC. TEST:" at 10217.23,281.64 h60
  text "NONE" at 11522.96,281.64 h60
  text "PER ORDER" at 12576.46,281.64 h60
  text "MANUFACTURER'S UL:" at 10217.23,124.64 h60
  text "RAIL" at 11382.96,120.35 h60
  text "METAL" at 11874.77,120.35 h60
  text "X" at 12250,120 h60
  text "SILK" at 12386.46,120.35 h60
  text ".Layer_Name" at -613,-1688.49 h60
M11 Gerber Information:
  lines w10: -1482,-1760.17 5118,-1760.17 ; -1482,-1556.83 5120,-1556.83 ; -1482,-1353.5 -1482,-1963.5 2523,-1963.5 5120,-1963.5 5120,-1353.5 -1481.5,-1353.5 -1481.5,-1963.5 94,-1963.5 ; 983,-1963.5 983,-1353.5 ; 2250,-1556.83 2250,-1353.5 ; 3090,-1556.83 3090,-1353.5 ; 3712,-1970 3712,-1767.17
  text "ALL ARTWORK VIEWED FROM TOP SIDE" at -1418.5,-1485.67 h60
  text "BOARD #:" at 1058,-1485.67 h60
  text ".PRJ_Number" at 1603.5,-1485.67 h60
  text "REV:" at 2448,-1485.67 h60
  text ".PCB_Rev" at 2739.5,-1485.67 h60
  text "SVN REV:" at 3286,-1485.67 h60
  text ".VersionControl_RevNumber" at 3792,-1485.67 h60
  text "LAYER NAME =" at -1418.5,-1688.49 h60
  text "PLOT NAME =" at -1418.5,-1894.34 h60
  text ".plot_File_Name" at -613,-1894.34 h60
  text "GENERATED    :" at 1060,-1894.34 h60
  text ".Print_Date" at 1929.5,-1894.34 h60
  text ".Print_Time" at 2658.5,-1894.34 h60
  text "TEXAS INSTRUMENTS" at 3923,-1894.34 h60
M12 Stackup:
  lines w6: 10170,6630 12720,6630 ; 10170,6734.4 12720,6734.4 ; 10110,6145 ccw(c10144,6145) 10144,6111 12746,6111 ccw(c12746,6145) 12780,6145 12780,6851 ccw(c12746,6851) 12746,6885 10144,6885 ccw(c10144,6851) 10110,6851 10110,6145
  text "The Stackup Legend below this is static." at 10415.5,7044.5 h60
  text "If you change the stackup, update the Legend." at 10425.5,6954.5 h60
  text "Layer Stack Up Detail for: Ref_Design.PcbDoc" at 10170,6767.1 h57
  text "Layer" at 10170,6695.4 h24
  text "Gerber" at 11065.81,6695.4 h24
  text "Copper" at 11629.33,6695.4 h24
  text "Dielectric" at 12232.04,6695.4 h24
  text "Name" at 10170,6647.4 h24
  text "Document" at 11065.81,6647.4 h24
  text "Thickness" at 11629.33,6647.4 h24
  text "Material" at 12232.04,6647.4 h24
  text "Top Solder Mask" at 10170,6554.44 h34
  text "(.GTS)" at 11065.81,6554.44 h34
  text "Solder Resist" at 12232.04,6554.44 h34
  text "Top Layer" at 10170,6457.69 h34
  text "(.GTL)" at 11065.81,6457.69 h34
  text "1.4mil" at 11629.33,6457.69 h34
  text "FR-4" at 12232.04,6409.31 h34
  text "Bottom Layer" at 10170,6360.94 h34
  text "(.GBL)" at 11065.81,6360.94 h34
  text "1.4mil" at 11629.33,6360.94 h34
  text "Bottom Solder Mask" at 10170,6264.19 h34
  text "(.GBS)" at 11065.81,6264.19 h34
  text "Solder Resist" at 12232.04,6264.19 h34
  text ".Layer_Name" at -613,-1688.49 h60
M13 Component Bodies Top:
  text ".Layer_Name" at -613,-1688.49 h60
M14 Component Bodies Bottom:
  text ".Layer_Name" at -613,-1688.49 h60
M15 Courtyards Top:
  text ".Layer_Name" at -613,-1688.49 h60
M16 Courtyards Bottom:
  text ".Layer_Name" at -613,-1688.49 h60
Drill Drawing:
  text ".Layer_Name" at -613,-1688.49 h60

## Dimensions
0,0 to 1440,0 on M2 Board Dimensions
0,0 to 0,2000 on M2 Board Dimensions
